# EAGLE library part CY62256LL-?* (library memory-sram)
256K (32K x 8) CMOS-Static RAM Source: http://download.cypress.com.edgesuite.net/design_resources/datasheets/contents/cy62256_8.pdf
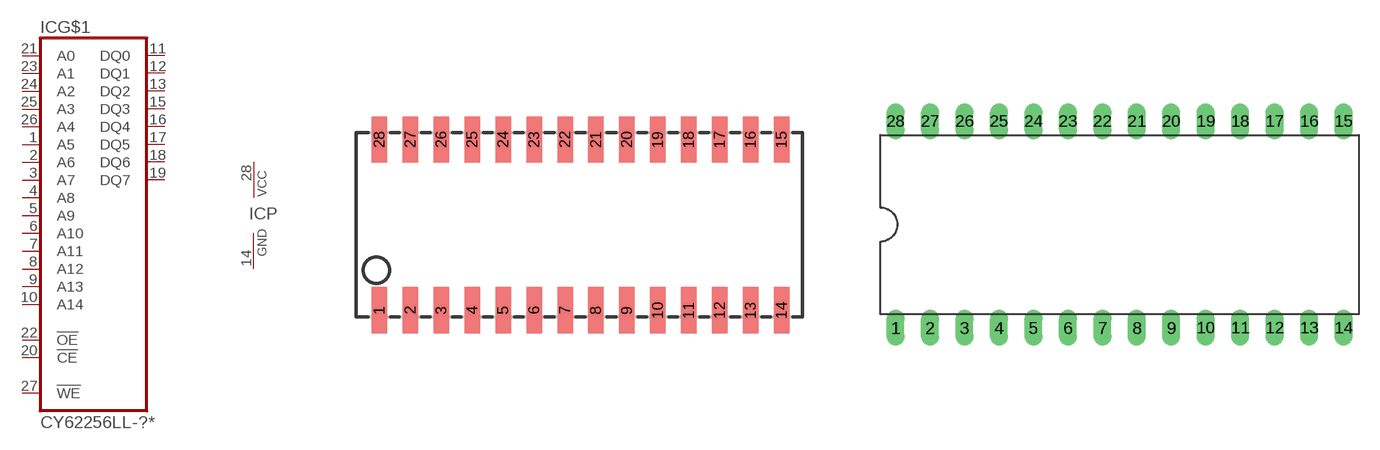
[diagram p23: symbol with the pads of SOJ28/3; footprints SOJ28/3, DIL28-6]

Designator prefix IC; gates G$1=LH52256 P=PWRN

## CY62256LL-SNC, CY62256LL-SNE, CY62256LL-SNI, CY62256LL-SNXC, CY62256LL-SNXE, CY62256LL-SNXI  [SOJ28/3]
1  G$1:A5  in
2  G$1:A6  in
3  G$1:A7  in
4  G$1:A8  in
5  G$1:A9  in
6  G$1:A10  in
7  G$1:A11  in
8  G$1:A12  in
9  G$1:A13  in
10  G$1:A14  in
11  G$1:DQ0
12  G$1:DQ1
13  G$1:DQ2
14  P:GND  pwr
15  G$1:DQ3
16  G$1:DQ4
17  G$1:DQ5
18  G$1:DQ6
19  G$1:DQ7
20  G$1:!CE  in
21  G$1:A0  in
22  G$1:!OE  in
23  G$1:A1  in
24  G$1:A2  in
25  G$1:A3  in
26  G$1:A4  in
27  G$1:!WE  in
28  P:VCC  pwr

## CY62256LL-PC, CY62256LL-PXC  [DIL28-6]
Pads as for SOJ28/3

## CY62256LL-ZC, CY62256LL-ZE, CY62256LL-ZXC, CY62256LL-ZXE, CY62256LL-ZXI  [TSOP1-28]
Pads as for SOJ28/3

## CY62256LL-ZRI, CY62256LL-ZRXE, CY62256LL-ZRXI  [TSOP1-28-R]
Pads as for SOJ28/3

## Footprint SOJ28/3 (pad centres in mm)
Small Outline J-Bend
smd 0.635 x 1.905: 1 -8.255,-3.505; 2 -6.985,-3.505; 3 -5.715,-3.505; 4 -4.445,-3.505; 5 -3.175,-3.505; 6 -1.905,-3.505; 7 -0.635,-3.505; 8 0.635,-3.505; 9 1.905,-3.505; 10 3.175,-3.505; 11 4.445,-3.505; 12 5.715,-3.505; 13 6.985,-3.505; 14 8.255,-3.505; 15 8.255,3.505; 16 6.985,3.505; 17 5.715,3.505; 18 4.445,3.505; 19 3.175,3.505; 20 1.905,3.505; 21 0.635,3.505; 22 -0.635,3.505; 23 -1.905,3.505; 24 -3.175,3.505; 25 -4.445,3.505; 26 -5.715,3.505; 27 -6.985,3.505; 28 -8.255,3.505

## Footprint DIL28-6 (pad centres in mm)
Dual In Line Package 0.6 inch
drill 0.813 long: 1 -16.51,-7.62; 2 -13.97,-7.62; 3 -11.43,-7.62; 4 -8.89,-7.62; 5 -6.35,-7.62; 6 -3.81,-7.62; 7 -1.27,-7.62; 8 1.27,-7.62; 9 3.81,-7.62; 10 6.35,-7.62; 11 8.89,-7.62; 12 11.43,-7.62; 13 13.97,-7.62; 14 16.51,-7.62; 15 16.51,7.62; 16 13.97,7.62; 17 11.43,7.62; 18 8.89,7.62; 19 6.35,7.62; 20 3.81,7.62; 21 1.27,7.62; 22 -1.27,7.62; 23 -3.81,7.62; 24 -6.35,7.62; 25 -8.89,7.62; 26 -11.43,7.62; 27 -13.97,7.62; 28 -16.51,7.62

## Footprint TSOP1-28 (pad centres in mm)
TSOP 1-28 28-pin Thin Small Outline Package Type 1 (8 x 13.4 mm) (51-85071) Source: http://download.cypress.com.edgesuite.net/design_resources/datasheets/contents/cy62256_8.pdf
smd 1 x 0.3: 1 -6.5,-0.275; 2 -6.5,-0.825; 3 -6.5,-1.375; 4 -6.5,-1.925; 5 -6.5,-2.475; 6 -6.5,-3.025; 7 -6.5,-3.575; 8 6.5,-3.575; 9 6.5,-3.025; 10 6.5,-2.475; 11 6.5,-1.925; 12 6.5,-1.375; 13 6.5,-0.825; 14 6.5,-0.275; 15 6.5,0.275; 16 6.5,0.825; 17 6.5,1.375; 18 6.5,1.925; 19 6.5,2.475; 20 6.5,3.025; 21 6.5,3.575; 22 -6.5,3.575; 23 -6.5,3.025; 24 -6.5,2.475; 25 -6.5,1.925; 26 -6.5,1.375; 27 -6.5,0.825; 28 -6.5,0.275

## Footprint TSOP1-28-R (pad centres in mm)
TSOP 1-28 R 28-pin Reverse Thin Small Outline Package Type 1 (8x13.4 mm) (51-85074) Source: http://download.cypress.com.edgesuite.net/design_resources/datasheets/contents/cy62256_8.pdf
smd 1 x 0.3: 1 -6.5,0.275; 2 -6.5,0.825; 3 -6.5,1.375; 4 -6.5,1.925; 5 -6.5,2.475; 6 -6.5,3.025; 7 -6.5,3.575; 8 6.5,3.575; 9 6.5,3.025; 10 6.5,2.475; 11 6.5,1.925; 12 6.5,1.375; 13 6.5,0.825; 14 6.5,0.275; 15 6.5,-0.275; 16 6.5,-0.825; 17 6.5,-1.375; 18 6.5,-1.925; 19 6.5,-2.475; 20 6.5,-3.025; 21 6.5,-3.575; 22 -6.5,-3.575; 23 -6.5,-3.025; 24 -6.5,-2.475; 25 -6.5,-1.925; 26 -6.5,-1.375; 27 -6.5,-0.825; 28 -6.5,-0.275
